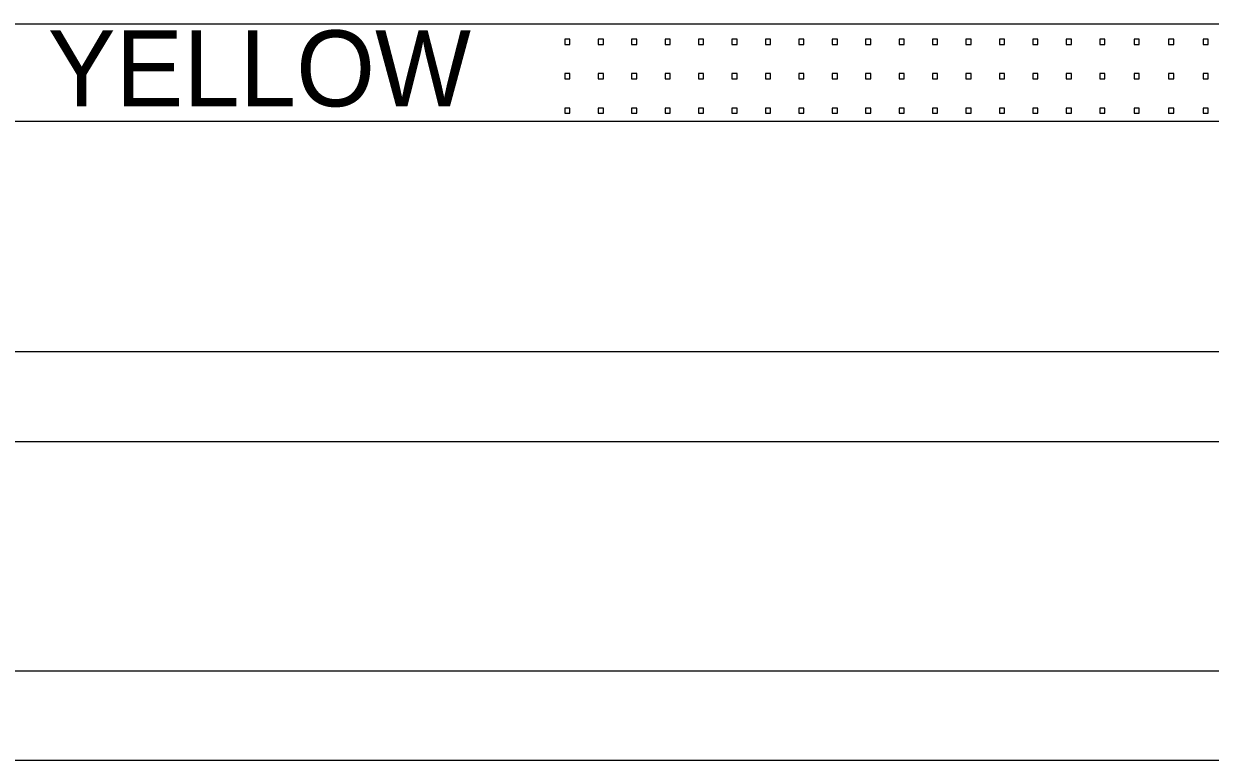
# Model space of a CAD drawing. Extents: x 15 to 764, y 7 to 487.
# Drawn here: x 526.6 to 581.3, y 105.2 to 139.2 of the extents above; entities that cross this region are included whole.
import ezdxf

# ---------------------------------------------------------------- set-up
doc = ezdxf.new("R2010")
doc.units = 0
doc.layers.add('Default', color=7, linetype='Continuous')
doc.layers.add('TextStructures', color=7, linetype='Continuous')

msp = doc.modelspace()

# ---------------------------------------------------------------- linework, layer by layer
at = {"layer": 'Default'}
for p, q in [((462.687, 139.163), (756.61, 139.163)), ((462.687, 134.675), (756.61, 134.675)), ((462.687, 124.052), (756.61, 124.052)), ((462.687, 119.905), (756.61, 119.905)), ((462.687, 109.343), (756.61, 109.343))]:
    msp.add_line(p, q, dxfattribs=at)
for points in [[(551.784, 138.212), (551.784, 138.452), (551.548, 138.451), (551.548, 138.212), (551.784, 138.212)], [(553.326, 138.212), (553.326, 138.452), (553.089, 138.451), (553.089, 138.212), (553.326, 138.212)], [(554.867, 138.212), (554.867, 138.452), (554.631, 138.451), (554.631, 138.212), (554.867, 138.212)], [(556.409, 138.212), (556.409, 138.452), (556.172, 138.451), (556.172, 138.212), (556.409, 138.212)], [(557.95, 138.212), (557.95, 138.452), (557.713, 138.451), (557.713, 138.212), (557.95, 138.212)], [(559.491, 138.212), (559.491, 138.452), (559.255, 138.451), (559.255, 138.212), (559.491, 138.212)], [(561.033, 138.212), (561.033, 138.452), (560.796, 138.451), (560.796, 138.212), (561.033, 138.212)], [(562.574, 138.212), (562.574, 138.452), (562.338, 138.451), (562.338, 138.212), (562.574, 138.212)], [(564.116, 138.212), (564.116, 138.452), (563.879, 138.451), (563.879, 138.212), (564.116, 138.212)], [(565.657, 138.212), (565.657, 138.452), (565.42, 138.451), (565.42, 138.212), (565.657, 138.212)], [(567.198, 138.212), (567.198, 138.452), (566.962, 138.451), (566.962, 138.212), (567.198, 138.212)], [(568.74, 138.212), (568.74, 138.452), (568.503, 138.451), (568.503, 138.212), (568.74, 138.212)], [(570.281, 138.212), (570.281, 138.452), (570.045, 138.451), (570.045, 138.212), (570.281, 138.212)], [(571.823, 138.212), (571.823, 138.452), (571.586, 138.451), (571.586, 138.212), (571.823, 138.212)], [(573.364, 138.212), (573.364, 138.452), (573.127, 138.451), (573.127, 138.212), (573.364, 138.212)], [(574.905, 138.212), (574.905, 138.452), (574.669, 138.451), (574.669, 138.212), (574.905, 138.212)], [(576.447, 138.212), (576.447, 138.452), (576.21, 138.451), (576.21, 138.212), (576.447, 138.212)], [(576.447, 138.212), (576.447, 138.452), (576.21, 138.451), (576.21, 138.212), (576.447, 138.212)], [(578.037, 138.212), (578.037, 138.452), (577.8, 138.451), (577.8, 138.212), (578.037, 138.212)], [(578.037, 138.212), (578.037, 138.452), (577.8, 138.451), (577.8, 138.212), (578.037, 138.212)], [(579.623, 138.212), (579.623, 138.452), (579.386, 138.451), (579.386, 138.212), (579.623, 138.212)], [(579.623, 138.212), (579.623, 138.452), (579.386, 138.451), (579.386, 138.212), (579.623, 138.212)], [(581.213, 138.212), (581.213, 138.452), (580.976, 138.451), (580.976, 138.212), (581.213, 138.212)], [(581.213, 138.212), (581.213, 138.452), (580.976, 138.451), (580.976, 138.212), (581.213, 138.212)], [(551.784, 136.624), (551.784, 136.863), (551.548, 136.862), (551.548, 136.624), (551.784, 136.624)], [(553.326, 136.624), (553.326, 136.863), (553.089, 136.862), (553.089, 136.624), (553.326, 136.624)], [(554.867, 136.624), (554.867, 136.863), (554.631, 136.862), (554.631, 136.624), (554.867, 136.624)], [(556.409, 136.624), (556.409, 136.863), (556.172, 136.862), (556.172, 136.624), (556.409, 136.624)], [(557.95, 136.624), (557.95, 136.863), (557.713, 136.862), (557.713, 136.624), (557.95, 136.624)], [(559.491, 136.624), (559.491, 136.863), (559.255, 136.862), (559.255, 136.624), (559.491, 136.624)], [(561.033, 136.624), (561.033, 136.863), (560.796, 136.862), (560.796, 136.624), (561.033, 136.624)], [(562.574, 136.624), (562.574, 136.863), (562.338, 136.862), (562.338, 136.624), (562.574, 136.624)], [(564.116, 136.624), (564.116, 136.863), (563.879, 136.862), (563.879, 136.624), (564.116, 136.624)], [(565.657, 136.624), (565.657, 136.863), (565.42, 136.862), (565.42, 136.624), (565.657, 136.624)], [(567.198, 136.624), (567.198, 136.863), (566.962, 136.862), (566.962, 136.624), (567.198, 136.624)], [(568.74, 136.624), (568.74, 136.863), (568.503, 136.862), (568.503, 136.624), (568.74, 136.624)], [(570.281, 136.624), (570.281, 136.863), (570.045, 136.862), (570.045, 136.624), (570.281, 136.624)], [(571.823, 136.624), (571.823, 136.863), (571.586, 136.862), (571.586, 136.624), (571.823, 136.624)], [(573.364, 136.624), (573.364, 136.863), (573.127, 136.862), (573.127, 136.624), (573.364, 136.624)], [(574.905, 136.624), (574.905, 136.863), (574.669, 136.862), (574.669, 136.624), (574.905, 136.624)], [(576.447, 136.624), (576.447, 136.863), (576.21, 136.862), (576.21, 136.624), (576.447, 136.624)], [(576.447, 136.624), (576.447, 136.863), (576.21, 136.862), (576.21, 136.624), (576.447, 136.624)], [(578.037, 136.624), (578.037, 136.863), (577.8, 136.862), (577.8, 136.624), (578.037, 136.624)], [(578.037, 136.624), (578.037, 136.863), (577.8, 136.862), (577.8, 136.624), (578.037, 136.624)], [(579.623, 136.624), (579.623, 136.863), (579.386, 136.862), (579.386, 136.624), (579.623, 136.624)], [(579.623, 136.624), (579.623, 136.863), (579.386, 136.862), (579.386, 136.624), (579.623, 136.624)], [(581.213, 136.624), (581.213, 136.863), (580.976, 136.862), (580.976, 136.624), (581.213, 136.624)], [(581.213, 136.624), (581.213, 136.863), (580.976, 136.862), (580.976, 136.624), (581.213, 136.624)], [(551.784, 135.036), (551.784, 135.276), (551.548, 135.275), (551.548, 135.036), (551.784, 135.036)], [(553.326, 135.036), (553.326, 135.276), (553.089, 135.275), (553.089, 135.036), (553.326, 135.036)], [(554.867, 135.036), (554.867, 135.276), (554.631, 135.275), (554.631, 135.036), (554.867, 135.036)], [(556.409, 135.036), (556.409, 135.276), (556.172, 135.275), (556.172, 135.036), (556.409, 135.036)], [(557.95, 135.036), (557.95, 135.276), (557.713, 135.275), (557.713, 135.036), (557.95, 135.036)], [(559.491, 135.036), (559.491, 135.276), (559.255, 135.275), (559.255, 135.036), (559.491, 135.036)], [(561.033, 135.036), (561.033, 135.276), (560.796, 135.275), (560.796, 135.036), (561.033, 135.036)], [(562.574, 135.036), (562.574, 135.276), (562.338, 135.275), (562.338, 135.036), (562.574, 135.036)], [(564.116, 135.036), (564.116, 135.276), (563.879, 135.275), (563.879, 135.036), (564.116, 135.036)], [(565.657, 135.036), (565.657, 135.276), (565.42, 135.275), (565.42, 135.036), (565.657, 135.036)], [(567.198, 135.036), (567.198, 135.276), (566.962, 135.275), (566.962, 135.036), (567.198, 135.036)], [(568.74, 135.036), (568.74, 135.276), (568.503, 135.275), (568.503, 135.036), (568.74, 135.036)], [(570.281, 135.036), (570.281, 135.276), (570.045, 135.275), (570.045, 135.036), (570.281, 135.036)], [(571.823, 135.036), (571.823, 135.276), (571.586, 135.275), (571.586, 135.036), (571.823, 135.036)], [(573.364, 135.036), (573.364, 135.276), (573.127, 135.275), (573.127, 135.036), (573.364, 135.036)], [(574.905, 135.036), (574.905, 135.276), (574.669, 135.275), (574.669, 135.036), (574.905, 135.036)], [(576.447, 135.036), (576.447, 135.276), (576.21, 135.275), (576.21, 135.036), (576.447, 135.036)], [(576.447, 135.036), (576.447, 135.276), (576.21, 135.275), (576.21, 135.036), (576.447, 135.036)], [(578.037, 135.036), (578.037, 135.276), (577.8, 135.275), (577.8, 135.036), (578.037, 135.036)], [(578.037, 135.036), (578.037, 135.276), (577.8, 135.275), (577.8, 135.036), (578.037, 135.036)], [(579.623, 135.036), (579.623, 135.276), (579.386, 135.275), (579.386, 135.036), (579.623, 135.036)], [(579.623, 135.036), (579.623, 135.276), (579.386, 135.275), (579.386, 135.036), (579.623, 135.036)], [(581.213, 135.036), (581.213, 135.276), (580.976, 135.275), (580.976, 135.036), (581.213, 135.036)], [(581.213, 135.036), (581.213, 135.276), (580.976, 135.275), (580.976, 135.036), (581.213, 135.036)]]:
    msp.add_lwpolyline(points, dxfattribs=at)
at = {"layer": 'TextStructures'}
msp.add_line((462.687, 105.216), (756.61, 105.216), dxfattribs=at)

# ---------------------------------------------------------------- texts
msp.add_text('YELLOW', height=3.5, rotation=0.0007, dxfattribs=at).set_placement((527.713, 135.356))

doc.saveas('drawing.dxf')
